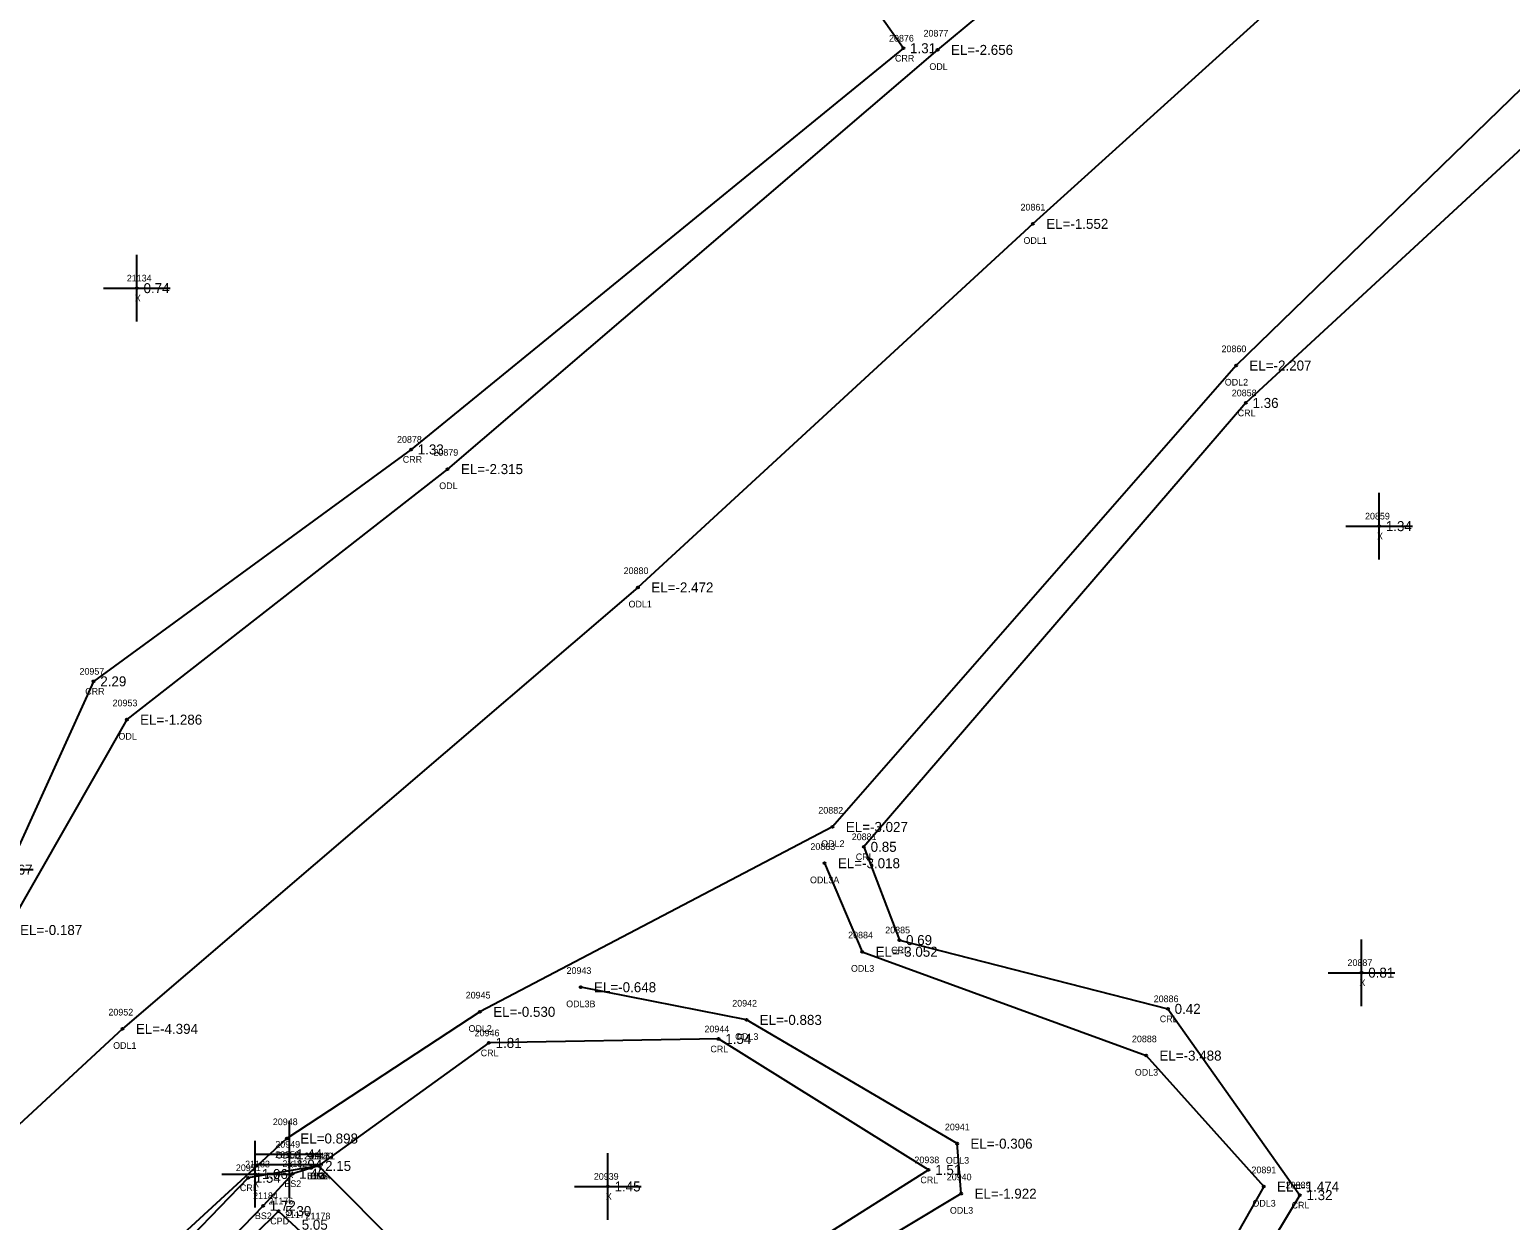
# Model space of a CAD drawing. Extents: x 2608745 to 2610333, y 641917 to 643463.
# Drawn here: x 2609542.9 to 2609764.9, y 642658.2 to 642836.7 of the extents above; entities that cross this region are included whole.
import ezdxf

# ---------------------------------------------------------------- set-up
doc = ezdxf.new("R2010")
doc.units = 0
for name, color, linetype in [('RD_DTM_BkLn2', 7, 'Continuous'), ('RD_DTM_BkLn_txCode', 7, 'Continuous'), ('RD_EX_Conc', 7, 'Continuous'), ('RD_EX_Conc_txCode', 7, 'Continuous'), ('RD_EX_H2O', 7, 'Continuous'), ('RD_EX_H2O_txCode', 7, 'Continuous'), ('RD_EX_Misc', 7, 'Continuous'), ('RD_EX_Misc_txCode', 7, 'Continuous'), ('RD_EX_TX_Conc_ELEV', 7, 'Continuous'), ('RD_EX_TX_H2O_ELEV', 7, 'Continuous'), ('RD_EX_TX_Misc_ELEV', 7, 'Continuous'), ('RD_SMD_Locator', 7, 'Continuous')]:
    doc.layers.add(name, color=color, linetype=linetype)

msp = doc.modelspace()

# ---------------------------------------------------------------- linework, layer by layer
at = {"layer": 'RD_DTM_BkLn2'}
msp.add_line((2609639.51, 642613.04), (2609586.16, 642666.36), dxfattribs=at)
msp.add_lwpolyline([(2609586.16, 642666.36), (2609582.27, 642665.19), (2609577.87, 642660.38), (2609555.26, 642637.05), (2609552.72, 642633.2), (2609570.22, 642608.05)], dxfattribs=at)
at = {"layer": 'RD_EX_Conc'}
msp.add_lwpolyline([(2609576.61, 642656.06), (2609580.19, 642659.59), (2609594.59, 642646.26), (2609590.88, 642642.24)], dxfattribs=at)
at = {"layer": 'RD_EX_H2O'}
for points in [[(2609918.81, 643009.04), (2609840.99, 642946.19), (2609752.78, 642894.89), (2609679.02, 642833.68), (2609605.53, 642770.83), (2609557.42, 642733.27), (2609539.43, 642701.73), (2609511.68, 642671.53), (2609423.05, 642632.06), (2609369.55, 642600.24), (2609327.57, 642579.96), (2609257.07, 642528.8), (2609194.6, 642443.8), (2609156.56, 642341.27)], [(2609920.46, 642991.11), (2609852.12, 642929.11), (2609767.83, 642874.99), (2609693.3, 642807.6), (2609634.08, 642753.09), (2609556.79, 642686.91), (2609524.97, 642657.54), (2609444.81, 642602.16), (2609373.09, 642552.33), (2609285.68, 642492.71), (2609230.49, 642411.33), (2609205.38, 642280.88)], [(2609940.72, 642981.52), (2609865.8, 642912.86), (2609792.29, 642852.87), (2609723.77, 642786.36), (2609663.25, 642717.18), (2609610.37, 642689.46), (2609581.45, 642670.47), (2609545.26, 642637.18), (2609509.19, 642582.86), (2609482.73, 642569.2), (2609408.72, 642506.3), (2609370.25, 642508.5), (2609327.7, 642455.81), (2609283.83, 642369.21), (2609262.12, 642251.22)], [(2609943.79, 642976.05), (2609869.55, 642907.14), (2609797.73, 642847.7), (2609725.24, 642780.75), (2609667.97, 642714.2), (2609673.28, 642700.22), (2609713.56, 642689.91), (2609733.33, 642661.98), (2609719.28, 642638.68), (2609663.61, 642631.91), (2609659.09, 642626.02), (2609711.84, 642571.44), (2609760.21, 642528.21), (2609792.62, 642516.23), (2609800.76, 642528.12), (2609797.45, 642563.99), (2609816.12, 642605.87)], [(2609601.98, 642935.78), (2609673.88, 642833.93), (2609600.06, 642773.78), (2609552.45, 642739.01), (2609536.34, 642703.62), (2609510.68, 642678.49), (2609498.28, 642669.79)], [(2609662.06, 642711.74), (2609667.71, 642698.47), (2609710.28, 642682.9), (2609727.91, 642663.26), (2609716.99, 642643.97), (2609660.46, 642637.14), (2609654.51, 642626.15), (2609709.09, 642568.34), (2609756.97, 642525.37), (2609791.92, 642510.53), (2609803.29, 642524.08), (2609799.58, 642559.74), (2609817.68, 642600.07)], [(2609827.02, 642593.77), (2609813.83, 642563.83), (2609821.87, 642523.17), (2609816.05, 642503.71), (2609776.93, 642503.96), (2609742.39, 642528.68), (2609685.39, 642563.92), (2609653.36, 642600.13), (2609643.82, 642618.08), (2609649.2, 642642.17), (2609682.55, 642662.2), (2609681.94, 642669.7), (2609650.34, 642688.25), (2609625.49, 642693.15)], [(2609830.46, 642590.52), (2609816.18, 642559.99), (2609824.93, 642525.1), (2609819.57, 642500.66), (2609777.53, 642499.54), (2609740.45, 642527.35), (2609685.03, 642559.92), (2609648.92, 642598.17), (2609639.51, 642613.04), (2609644.31, 642644.72), (2609677.66, 642665.76), (2609646.17, 642685.39), (2609611.73, 642684.8), (2609586.16, 642666.36), (2609575.62, 642664.58), (2609550.15, 642638.19)]]:
    msp.add_lwpolyline(points, dxfattribs=at)
at = {"layer": 'RD_EX_Misc'}
for p, q in [((2609558.94, 642792.96), (2609558.94, 642802.96)), ((2609553.94, 642797.96), (2609563.94, 642797.96)), ((2609745.23, 642757.28), (2609745.23, 642767.28)), ((2609740.23, 642762.28), (2609750.23, 642762.28)), ((2609533.39, 642710.78), (2609543.39, 642710.78)), ((2609742.59, 642690.33), (2609742.59, 642700.33)), ((2609737.59, 642695.33), (2609747.59, 642695.33)), ((2609581.82, 642663.1), (2609581.82, 642673.1)), ((2609581.83, 642661.55), (2609581.83, 642671.55)), ((2609576.68, 642660.14), (2609576.68, 642670.14)), ((2609576.82, 642668.1), (2609586.82, 642668.1)), ((2609576.83, 642666.55), (2609586.83, 642666.55)), ((2609629.57, 642658.28), (2609629.57, 642668.28)), ((2609571.68, 642665.14), (2609581.68, 642665.14)), ((2609624.57, 642663.28), (2609634.57, 642663.28))]:
    msp.add_line(p, q, dxfattribs=at)
at = {"layer": 'RD_SMD_Locator'}
for centre in [(2609673.88, 642833.93), (2609679.02, 642833.68), (2609693.3, 642807.6), (2609558.94, 642797.96), (2609723.77, 642786.36), (2609725.24, 642780.75), (2609600.06, 642773.78), (2609605.53, 642770.83), (2609745.23, 642762.28), (2609634.08, 642753.09), (2609552.45, 642739.01), (2609557.42, 642733.27), (2609663.25, 642717.18), (2609667.97, 642714.2), (2609662.06, 642711.74), (2609673.28, 642700.22), (2609667.71, 642698.47), (2609742.59, 642695.33), (2609625.49, 642693.15), (2609610.37, 642689.46), (2609713.56, 642689.91), (2609556.79, 642686.91), (2609650.34, 642688.25), (2609611.73, 642684.8), (2609646.17, 642685.39), (2609710.28, 642682.9), (2609581.45, 642670.47), (2609681.94, 642669.7), (2609581.82, 642668.1), (2609581.83, 642666.55), (2609586.16, 642666.36), (2609586.16, 642666.36), (2609586.16, 642666.36), (2609575.62, 642664.58), (2609576.68, 642665.14), (2609582.27, 642665.19), (2609677.66, 642665.76), (2609629.57, 642663.28), (2609682.55, 642662.2), (2609727.91, 642663.26), (2609733.33, 642661.98), (2609577.87, 642660.38), (2609580.19, 642659.59)]:
    msp.add_circle(centre, 0.15, dxfattribs=at)

# ---------------------------------------------------------------- texts
at = {"layer": 'RD_DTM_BkLn_txCode'}
for s, p in [('21182', (2609580.76, 642666.19)), ('21180', (2609584.61, 642667.36)), ('21181', (2609584.93, 642667.36)), ('BS2', (2609581.05, 642663.19)), ('BS2A', (2609584.45, 642664.36)), ('BSB', (2609584.91, 642664.36)), ('21184', (2609576.36, 642661.38)), ('BS2', (2609576.64, 642658.38)), ('21177', (2609581.15, 642658.54)), ('21178', (2609584.24, 642658.34))]:
    msp.add_text(s, height=1, dxfattribs=at).set_placement(p)
at = {"layer": 'RD_EX_Conc_txCode'}
for s, p in [('21176', (2609578.66, 642660.59)), ('CPD', (2609578.94, 642657.59))]:
    msp.add_text(s, height=1, dxfattribs=at).set_placement(p)
at = {"layer": 'RD_EX_H2O_txCode'}
for s, p in [('20876', (2609671.73, 642834.93)), ('20877', (2609676.9, 642835.68)), ('CRR', (2609672.62, 642831.93)), ('ODL', (2609677.78, 642830.68)), ('20861', (2609691.45, 642809.6)), ('ODL1', (2609691.89, 642804.6)), ('20860', (2609721.59, 642788.36)), ('ODL2', (2609722.08, 642783.36)), ('20858', (2609723.13, 642781.75)), ('CRL', (2609724.02, 642778.75)), ('20878', (2609597.95, 642774.78)), ('20879', (2609603.41, 642772.83)), ('CRR', (2609598.81, 642771.78)), ('ODL', (2609604.28, 642767.83)), ('20880', (2609631.93, 642755.09)), ('ODL1', (2609632.67, 642750.09)), ('20957', (2609550.33, 642740.01)), ('CRR', (2609551.19, 642737.01)), ('20953', (2609555.3, 642735.27)), ('ODL', (2609556.18, 642730.27)), ('20882', (2609661.13, 642719.18)), ('ODL2', (2609661.56, 642714.18)), ('20881', (2609666.14, 642715.2)), ('20883', (2609659.94, 642713.74)), ('CRL', (2609666.74, 642712.2)), ('ODL3A', (2609659.88, 642708.74)), ('20885', (2609671.16, 642701.22)), ('20884', (2609665.6, 642700.47)), ('CRL', (2609672.05, 642698.22)), ('20943', (2609623.37, 642695.15)), ('ODL3', (2609666.02, 642695.47)), ('20945', (2609608.25, 642691.46)), ('ODL3B', (2609623.32, 642690.15)), ('20942', (2609648.22, 642690.25)), ('20886', (2609711.42, 642690.91)), ('20952', (2609554.67, 642688.91)), ('CRL', (2609712.33, 642687.91)), ('ODL2', (2609608.67, 642686.46)), ('20946', (2609609.59, 642685.8)), ('20944', (2609644.05, 642686.39)), ('ODL3', (2609648.65, 642685.25)), ('ODL1', (2609555.38, 642683.91)), ('CRL', (2609644.94, 642683.39)), ('20888', (2609708.16, 642684.9)), ('CRL', (2609610.5, 642682.8)), ('ODL3', (2609708.59, 642679.9)), ('20948', (2609579.33, 642672.47)), ('20941', (2609680.11, 642671.7)), ('ODL2', (2609579.76, 642667.47)), ('20951', (2609573.78, 642665.58)), ('20947', (2609584.04, 642667.36)), ('20938', (2609675.54, 642666.76)), ('ODL3', (2609680.25, 642666.7)), ('20891', (2609726.08, 642665.26)), ('CRL', (2609584.93, 642664.36)), ('CRL', (2609676.43, 642663.76)), ('20940', (2609680.39, 642664.2)), ('CRL', (2609574.39, 642662.58)), ('20889', (2609731.21, 642662.98)), ('ODL3', (2609680.86, 642659.2)), ('ODL3', (2609726.22, 642660.26)), ('CRL', (2609732.1, 642659.98))]:
    msp.add_text(s, height=1, dxfattribs=at).set_placement(p)
at = {"layer": 'RD_EX_Misc_txCode'}
for s, p in [('21134', (2609557.43, 642798.96)), ('X', (2609558.63, 642795.96)), ('20859', (2609743.11, 642763.28)), ('X', (2609744.91, 642760.28)), ('20887', (2609740.48, 642696.33)), ('X', (2609742.28, 642693.33)), ('20950', (2609579.67, 642667.55)), ('20949', (2609579.7, 642669.1)), ('21183', (2609575.17, 642666.14)), ('X', (2609581.5, 642666.1)), ('X', (2609576.37, 642663.14)), ('X', (2609581.51, 642664.55)), ('20939', (2609627.46, 642664.28)), ('X', (2609629.26, 642661.28))]:
    msp.add_text(s, height=1, dxfattribs=at).set_placement(p)
at = {"layer": 'RD_EX_TX_Conc_ELEV'}
msp.add_text('5.30', height=1.5, dxfattribs=at).set_placement((2609581.19, 642658.84))
at = {"layer": 'RD_EX_TX_H2O_ELEV'}
for s, p in [('1.31', (2609674.88, 642833.18)), ('EL=-2.656', (2609681.02, 642832.93)), ('EL=-1.552', (2609695.3, 642806.85)), ('EL=-2.207', (2609725.77, 642785.61)), ('1.36', (2609726.24, 642780)), ('1.33', (2609601.06, 642773.03)), ('EL=-2.315', (2609607.53, 642770.08)), ('EL=-2.472', (2609636.08, 642752.34)), ('2.29', (2609553.45, 642738.26)), ('EL=-1.286', (2609559.42, 642732.52)), ('EL=-3.027', (2609665.25, 642716.43)), ('0.85', (2609668.97, 642713.45)), ('EL=-3.018', (2609664.06, 642710.99)), ('EL=-0.187', (2609541.43, 642700.98)), ('0.69', (2609674.28, 642699.47)), ('EL=-3.052', (2609669.71, 642697.72)), ('EL=-0.648', (2609627.49, 642692.4)), ('0.42', (2609714.56, 642689.16)), ('EL=-0.530', (2609612.37, 642688.71)), ('EL=-0.883', (2609652.34, 642687.5)), ('EL=-4.394', (2609558.79, 642686.16)), ('1.81', (2609612.73, 642684.05)), ('1.54', (2609647.17, 642684.64)), ('EL=-3.488', (2609712.28, 642682.15)), ('EL=0.898', (2609583.45, 642669.72)), ('EL=-0.306', (2609683.94, 642668.95)), ('2.15', (2609587.16, 642665.61)), ('1.51', (2609678.66, 642665.01)), ('1.54', (2609576.62, 642663.83)), ('EL=-1.922', (2609684.55, 642661.45)), ('EL=-1.474', (2609729.91, 642662.51)), ('1.32', (2609734.33, 642661.23))]:
    msp.add_text(s, height=1.5, dxfattribs=at).set_placement(p)
at = {"layer": 'RD_EX_TX_Misc_ELEV'}
for s, p in [('0.74', (2609559.94, 642797.21)), ('1.34', (2609746.23, 642761.53)), ('1.67', (2609539.39, 642710.03)), ('0.81', (2609743.59, 642694.58)), ('1.44', (2609582.82, 642667.35)), ('1.94', (2609582.83, 642665.8)), ('2.15', (2609587.16, 642665.61)), ('2.15', (2609587.16, 642665.61)), ('1.06', (2609577.68, 642664.39)), ('1.46', (2609583.27, 642664.44)), ('1.45', (2609630.57, 642662.53)), ('1.72', (2609578.87, 642659.63)), ('5.05', (2609583.66, 642656.79))]:
    msp.add_text(s, height=1.5, dxfattribs=at).set_placement(p)

doc.saveas('drawing.dxf')
